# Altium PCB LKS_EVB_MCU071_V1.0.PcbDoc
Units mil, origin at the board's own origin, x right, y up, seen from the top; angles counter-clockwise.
Board outline 2625 x 1560 mil, 2 copper layers (Top Layer, Bottom Layer); 45 components, 64 nets, 192 pads, 49 vias.
Unrouted connection lines stored in the file: 4.
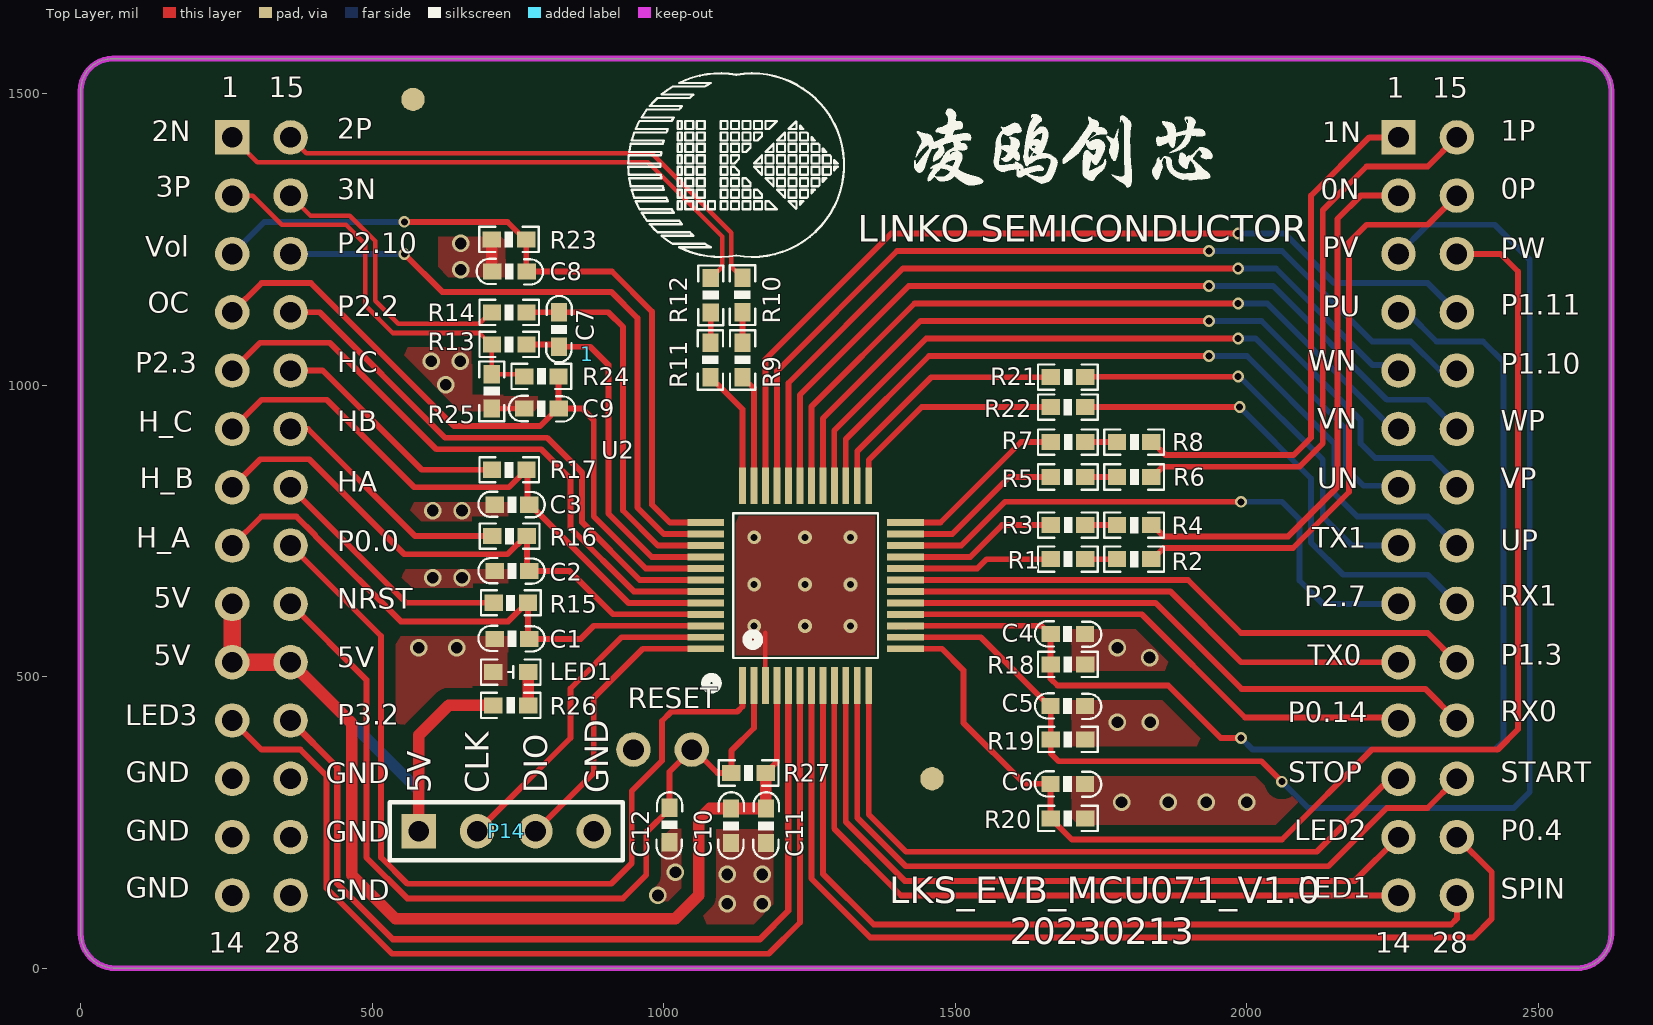
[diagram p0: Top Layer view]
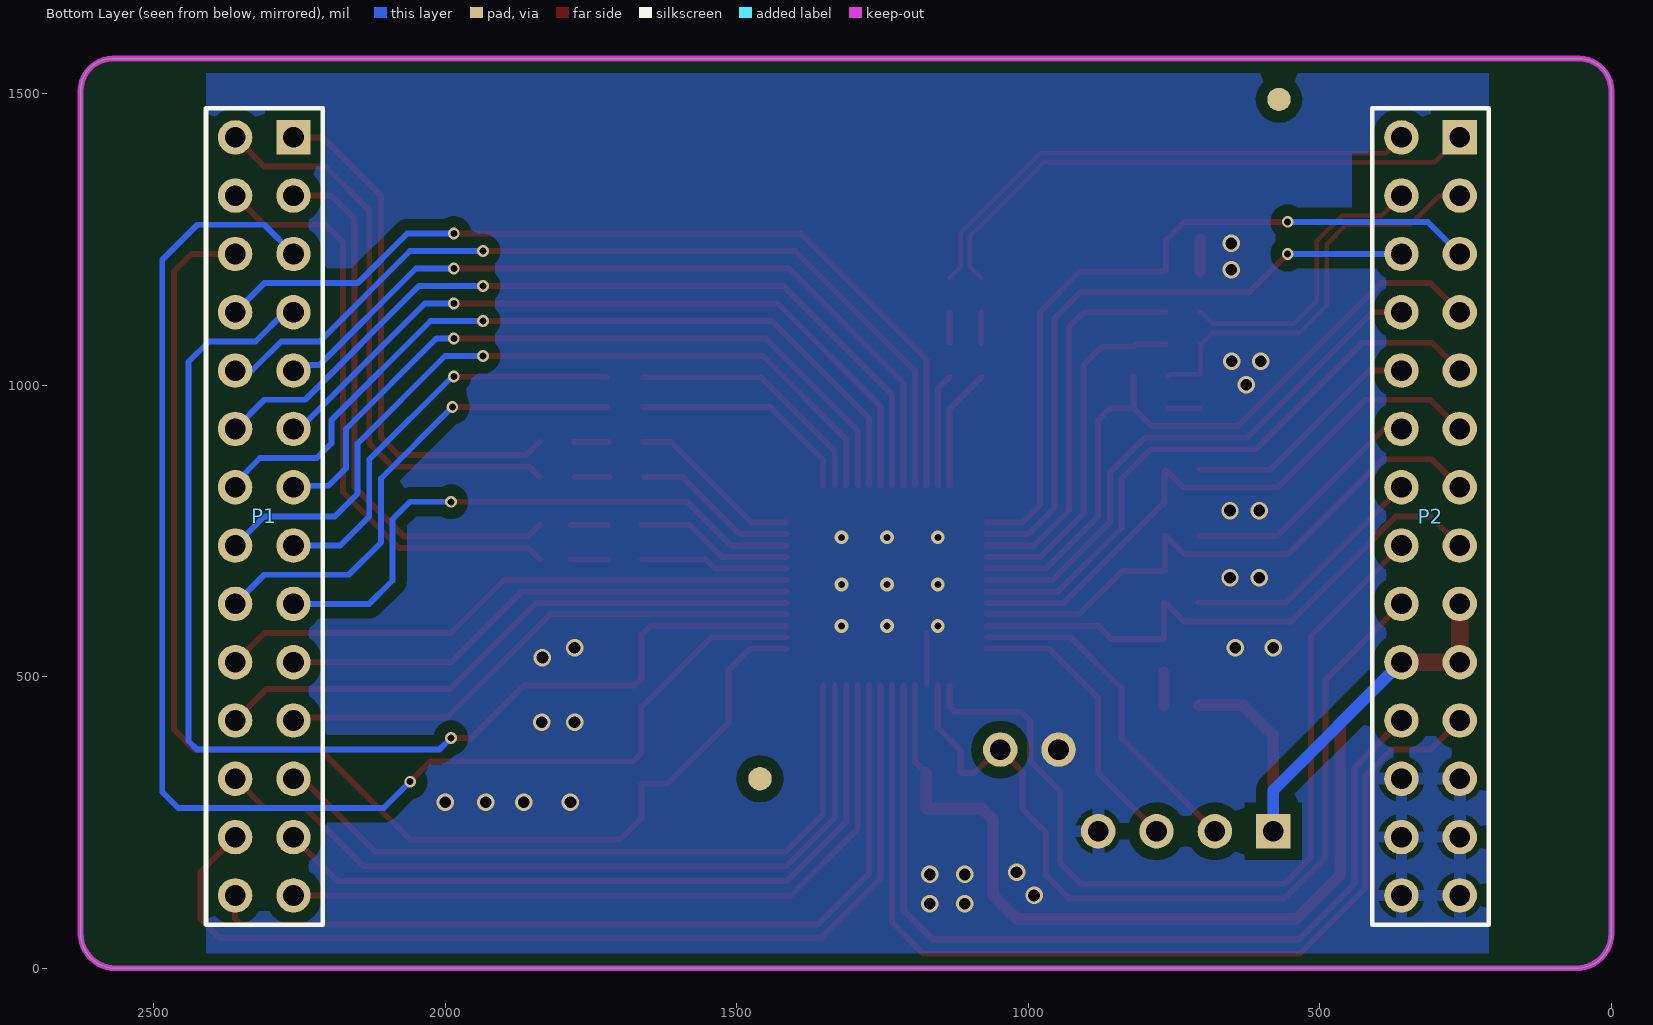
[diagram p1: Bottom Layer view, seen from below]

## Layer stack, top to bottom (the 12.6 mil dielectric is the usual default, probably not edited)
Top Solder: solder mask 0.4, Solder Resist, Dk 3.5
Top Layer: signal copper 1.4
Dielectric1: dielectric 12.6, FR-4, Dk 4.8
Bottom Layer: signal copper 1.4
Bottom Solder: solder mask 0.4, Solder Resist, Dk 3.5

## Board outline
0,60 0,1505 cw(c55,1505) 55,1560 2570,1560 cw(c2570,1505) 2625,1505 2625,60 cw(c2565,60) 2565,0 60,0 cw(c60,60)

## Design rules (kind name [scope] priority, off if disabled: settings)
Clearance Clearance_2 [InPolygon] p1: gap=20 ignorepadtopadclearanceinfootprint=FALSE except(0: Arc-Hole Track-Hole SMDPad-Hole THPad-Hole Via-Hole Fill-Hole Poly-Hole Region-Hole Text-Hole)
Clearance Clearance_1 [All] p2: gap=7.87 ignorepadtopadclearanceinfootprint=FALSE except(0: Arc-Hole Track-Hole SMDPad-Hole THPad-Hole Via-Hole Fill-Hole Poly-Hole Region-Hole Text-Hole)
ComponentClearance [All] p1: gap=0 collisioncheckmode=3 verticalgap=0 showdistances=FALSE
DiffPairsRouting [All] p1: maxlimit=10 minlimit=10 mostfreqgap=10 toplayer_minwidth=8 toplayer_maxwidth=15 toplayer_prefwidth=10 bottomlayer_minwidth=8 bottomlayer_maxwidth=15 bottomlayer_prefwidth=10 maxuncoupledlength=500
FabricationTestpoint [(IsPad And (OnTopLayer Or OnBottomLayer))] p1: side=3 testpointundercomponent=TRUE minsize=40 maxsize=100 preferedsize=60 minholesize=0 maxholesize=40 preferedholesize=32 testpointgrid=1 allowsidetop=TRUE allowsidebottom=TRUE usegrid=TRUE gridtolerance=0.01
HoleSize [All] p1: absolutevalues=TRUE maxlimit=100 minlimit=0 maxpercent=80.000 minpercent=20.000
PolygonConnect PolygonConnect_2 [HasFootprint('HDR1X4') vs InNet('GND')] p1: connectstyle=Relief reliefconductorwidth=20 reliefentries=4 polygonreliefangle="90 Angle" airgapwidth=10
PolygonConnect PolygonConnect_1 [HasFootprint('HDR2X14_CEN') vs InNet('GND')] p2: connectstyle=Relief reliefconductorwidth=20 reliefentries=4 polygonreliefangle="90 Angle" airgapwidth=10
PolygonConnect [All] p3: connectstyle=Direct reliefconductorwidth=10 reliefentries=4 polygonreliefangle="90 Angle" airgapwidth=10
RoutingVias [All] p1: holewidth=28 width=50 viastyle="Through Hole" minholewidth=0 minwidth=10 maxholewidth=28 maxwidth=50
SilkToSolderMaskClearance SilkscreenOverComponentPads [IsPad] p1: minsilkscreentomaskgap=10 clearancetoexposedcopper=TRUE
SolderMaskExpansion [All] p1: expansion=4 istentingtop=FALSE
Width [All] p1: maxlimit=100 minlimit=1 preferedwidth=10
25 further rules are at their usual default settings.

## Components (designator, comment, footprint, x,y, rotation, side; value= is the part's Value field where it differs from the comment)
1 "LKS_sign" LKS_LOGO2 868.94,1052.83 r0 top
C1 "10nF/50V" 0603C 769.06,565 r180 top
C2 "10nF/50V" 0603C 769.06,681.13 r180 top
C3 "10nF/50V" 0603C 769.06,795 r180 top
C4 "1nF/50V" 0603C 1663.34,573.64 r0 top
C5 "1nF/50V" 0603C 1663.2,450 r0 top
C6 "1nF/50V" 0603C 1663.2,316.45 r0 top
C7 "1nF/50V" 0603C 820,1065.94 r90 top
C8 "100nF/50V" 0603C 705.94,1195 r0 top
C9 "1nF/50V" 0603C 760.94,960 r0 top
C10 "10uF/16V" 0603C 1115,215 r90 top
C11 "100nF/50V" 0603C 1175,215 r90 top
C12 "100nF/50V" 0603C 1010,275.24 r270 top
LED1 "LED" "LED 0603R" 737.57,508 r180 top
P1 "Header 14X2A" HDR2X14_CEN 2260,1425 r270 bottom locked
P2 "Header 14X2A" HDR2X14_CEN 260,1425 r270 bottom locked
P14 "Header 4" HDR1X4 580,235 r0 top
R1 "20K1%" 0603R#1 1722.56,701.59 r180 top value=K
R2 "20K1%" 0603R#1 1836.22,701.59 r180 top value=K
R3 "20K1%" 0603R#1 1722.56,760 r180 top value=K
R4 "20K1%" 0603R#1 1836.22,760 r180 top value=K
R5 "20K1%" 0603R#1 1722.56,842.52 r180 top value=K
R6 "20K1%" 0603R#1 1836.22,842.52 r180 top value=K
R7 "20K1%" 0603R#1 1722.56,902.52 r180 top value=K
R8 "20K1%" 0603R#1 1836.22,902.52 r180 top value=K
R9 "20K1%" 0603R#1 1135.08,1072.79 r270 top value=K
R10 "20K1%" 0603R#1 1135,1184.06 r270 top value=K
R11 "20K1%" 0603R#1 1080.05,1072.79 r270 top value=K
R12 "20K1%" 0603R#1 1080.6,1183.74 r270 top value=K
R13 "1K1%" 0603R#1 705.5,1070 r0 top value=K
R14 "1K1%" 0603R#1 705.5,1125 r0 top value=K
R15 "2K" 0603R#1 708.22,626.9 r0 top value=K
R16 "2K" 0603R#1 706.13,741.13 r0 top value=K
R17 "2K" 0603R#1 705.5,855 r0 top value=K
R18 "1K" 0603R#1 1663.5,521.25 r0 top value=K
R19 "1K" 0603R#1 1663.5,392.6 r0 top value=K
R20 "1K" 0603R#1 1663.5,257.18 r0 top value=K
R21 "10R" 0603R#1 1722.56,1013.7 r180 top value=K
R22 "10R" 0603R#1 1663.5,962.52 r0 top value=K
R23 "1K1%" 0603R#1 705,1250 r0 top value=K
R24 "1K1%" 0603R#1 819.56,1015 r180 top value=K
R25 "10R" 0603R#1 705,1019.06 r270 top value=K
R26 "330R" 0603R#2 737.57,451 r0 top value=330
R27 "20K" 0603R#1 1115.94,335 r0 top value=K
U2 "LKS32MC071CBT8" TQFP48 1243.27,656.26 r0 top

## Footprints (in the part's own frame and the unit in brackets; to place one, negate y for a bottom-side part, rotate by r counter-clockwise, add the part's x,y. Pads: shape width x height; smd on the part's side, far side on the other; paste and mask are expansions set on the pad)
0603C [mm]
  rect 0.8x0.7 smd: 1(0,0) 2(1.5,0)
  silkscreen extent -0.68,-0.57 2.21,0.55
0603R#1 [mm]
  rect 0.8x0.7 smd: 1(0,0) 2(1.5,0)
  silkscreen extent -0.55,-0.55 2.05,0.55
0603R#2 [mm] "电阻"
  rect 0.8x0.7 smd: 1(-0.762,0) 2(0.762,0)
  silkscreen extent -1.3,-0.55 1.3,0.55, body extent -0.8,-0.4 0.8,0.4, height 0.45
HDR1X4 [mm] "Connector; Header; 4 Position"
  rect 1.5x1.5 hole 0.9: 1(0,0)
  round 1.5 hole 0.9: 2(2.54,0) 3(5.08,0) 4(7.62,0)
  silkscreen extent -1.27,-1.27 8.89,1.27
HDR2X14_CEN [mm] "Connector; Header; 14x2 Position"
  rect 1.5x1.5 hole 0.9: 1(0,0)
  round 1.5 hole 0.9: 2(2.54,0) 3(5.08,0) 4(7.62,0) 5(10.16,0) 6(12.7,0) 7(15.24,0) 8(17.78,0) 9(20.32,0) 10(22.86,0) 11(25.4,0) 12(27.94,0) 13(30.48,0) 14(33.02,0) 15(0,-2.54) 16(2.54,-2.54) 17(5.08,-2.54) 18(7.62,-2.54) 19(10.16,-2.54) 20(12.7,-2.54) 21(15.24,-2.54) 22(17.78,-2.54) 23(20.32,-2.54) 24(22.86,-2.54) 25(25.4,-2.54) 26(27.94,-2.54) 27(30.48,-2.54) 28(33.02,-2.54)
  silkscreen extent -1.27,-3.81 34.29,1.27
"LED 0603R" [mm] "LED"
  rect 0.8x0.7 smd: 1(-0.762,0) 2(0.762,0)
  silkscreen extent -1.3,-0.55 1.3,0.55, body extent -0.8,-0.4 0.8,0.4, height 0.47
LKS_LOGO2 [mil] "标?"
  silkscreen extent 70,167 440,482
TQFP48 [mm] "LINKO-081/083/088/051"
  rect 0.3x1.6 smd: 1(-2.75,-4.35) 2(-2.25,-4.35) 3(-1.75,-4.35) 4(-1.25,-4.35) 5(-0.75,-4.35) 6(-0.25,-4.35) 7(0.25,-4.35) 8(0.75,-4.35) 9(1.25,-4.35) 10(1.75,-4.35) 11(2.25,-4.35) 12(2.75,-4.35) 25(2.75,4.35) 26(2.25,4.35) 27(1.75,4.35) 28(1.25,4.35) 29(0.75,4.35) 30(0.25,4.35) 31(-0.25,4.35) 32(-0.75,4.35) 33(-1.25,4.35) 34(-1.75,4.35) 35(-2.25,4.35) 36(-2.75,4.35)
  rect 1.6x0.3 smd: 13(4.35,-2.75) 14(4.35,-2.25) 15(4.35,-1.75) 16(4.35,-1.25) 17(4.35,-0.75) 18(4.35,-0.25) 19(4.35,0.25) 20(4.35,0.75) 21(4.35,1.25) 22(4.35,1.75) 23(4.35,2.25) 24(4.35,2.75) 37(-4.35,2.75) 38(-4.35,2.25) 39(-4.35,1.75) 40(-4.35,1.25) 41(-4.35,0.75) 42(-4.35,0.25) 43(-4.35,-0.25) 44(-4.35,-0.75) 45(-4.35,-1.25) 46(-4.35,-1.75) 47(-4.35,-2.25) 48(-4.35,-2.75)
  silkscreen extent -4.35,-4.5 3.15,3.15, body extent -4.5,-4.5 4.5,4.5, height 1.05

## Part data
C1 C2 C3 C4 C5 C6: library part CAP, "Capacitor"
C7 C8 C9 C10 C11 C12: library part C, "Capacitor"
LED1: "LED_Light"
P1 P2: "Header, 14-Pin, Dual row"
P14: "Header, 4-Pin"
R1 R2 R3 R4 R5 R6 R7 R8 R9 R10 R11 R12 R13 R14 R15 R16 R17 R18 R19 R20 R21 R22 R23 R24 R25 R26 R27: library part Res, "Resistor"
U2: "芯片"

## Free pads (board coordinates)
  round 59.06 hole 35.43: 0(1048,375) 1(948,375)
  round 40 all layers, no hole: 2(1460,325) 3(570,1490)

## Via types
v1: diameter 30, hole 20, Top Layer to Bottom Layer, 25 vias
v2: diameter 20, hole 12, Top Layer to Bottom Layer, 15 vias
v3: diameter 23.62, hole 11.81, Top Layer to Bottom Layer, 9 vias

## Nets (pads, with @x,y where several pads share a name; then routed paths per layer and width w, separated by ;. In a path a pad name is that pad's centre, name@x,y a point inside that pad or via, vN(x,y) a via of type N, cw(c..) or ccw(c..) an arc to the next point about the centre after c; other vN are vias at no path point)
+5V: C10.2 C11.2 P2.9 P2.10 P2.24 P14.1 R26.1 R27.2 U2.4 | length 2417.7
  Top Layer w10: R27.2 1194.06,354.06 U2.4
  Top Layer w20: P2.24 465,420 465,160 540,85 1020,85 1060,125 1060,255 1079.06,274.06 C10.2 C11.2 R27.2 ; P14.1 580,400 631,451 R26.1
  Top Layer w30: P2.9 P2.10 P2.24
  Bottom Layer w20: P2.24 580,305 P14.1
GND: C1.2 C2.2 C3.2 C4.2 C5.2 C6.2 C8.1 C9.1 C10.1 C11.1 C12.2 LED1.2 P2.12 P2.13 P2.14 P2.16 P2.26 P2.27 P2.28 P14.4 pad.1 R14.1 R18.2 R19.2 R20.2 R23.1 R25.2 U2.3 | length 706.5
  Top Layer w7.87: P2.16 394.25,1290.75 461.52,1290.75 505,1247.27 505,1145 544.81,1105.19 683.72,1105.19 703.53,1125 R14.1 ; R25.2 C9.1 ; C8.1@705,1195.94 C8.1 ; U2.3 1174.37,575.51
  Top Layer w20: C8.1@705,1195.94 R23.1
  other v1: 1109,111 1169,111 990,125 1109,161 1169,161 1020,165 1785,285 1865,285 1930,285 2000,285 1778,422 1834,422 1833,533 580,550 645,550 1778,550 604,670 654,670 604,785 654,785 626,1001 601,1041 651,1041 652,1198 652,1243
  other v3: 1155,587.04 1242,587.04 1320,587.04 1155,658 1242,658 1320,658 1155,739.07 1242,739.07 1320,739.07
HALL_U: C1.1 P2.8 R15.2 U2.46 | length 991.2
  Top Layer w10: P2.8 310,775 369.96,775 402.4,742.56 402.4,741.55 548.95,595 733.41,595 765.31,626.9 R15.2 767.28,566.78 C1.1 857.64,565 880,587.36 U2.46
HALL_V: C2.1 P2.7 R16.2 U2.45 | length 1002.7
  Top Layer w10: P2.7 307.99,872.99 392.01,872.99 555,710 732.08,710 763.21,741.13 R16.2 765.65,740.66 765.65,681.13 838.87,681.13 912.95,607.05 U2.45
HALL_W: C3.1 P2.6 R17.2 U2.44 | length 1035.9
  Top Layer w10: P2.6 310,975 421.96,975 571.96,825 734.56,825 R17.2 766.33,853.23 766.33,795 C3.1 771.02,795 939.29,626.73 U2.44
HU: P2.21 R15.1 | length 430.3
  Top Layer w10: P2.21 558.1,626.9 R15.1
HV: P2.20 R16.1 | length 422.3
  Top Layer w10: P2.20 389.75,925 573.62,741.13 R16.1
HW: P2.19 R17.1 | length 415.9
  Top Layer w10: P2.19 415,1025 585,855 R17.1
LED1: P1.14 U2.9 | length 1260.4
  Top Layer w10: U2.9 1292.48,239.52 1407,125 P1.14
LED2: P1.13 U2.10 | length 1254.6
  Top Layer w10: U2.10 1312.17,251.15 1413.32,150 2185,150 P1.13
LED3: P2.11 U2.6 | length 1680.9
  Top Layer w10: P2.11 310,375 377.01,375 421.63,330.38 421.63,137.39 534.02,25 1180,25 1233.43,78.43 U2.6
NetLED1_1: LED1.1 R26.2 | length 57
  Top Layer w20: R26.2 LED1.1
NetR1_1: R1.1 R2.2 | length 63.6
  Top Layer w10: R1.1@1721.39,701.59 R2.2@1785,701.59
NetR3_1: R3.1 R4.2 | length 63.9
  Top Layer w10: R3.1@1721.1,760 R4.2@1785,760
NetR5_1: R5.1 R6.2 | length 59.1
  Top Layer w10: R5.1@1718.11,842.52 R6.2
NetR7_1: R7.1 R8.2 | length 59.1
  Top Layer w10: R7.1@1720.04,902.52 R8.2@1779.09,902.52
NetR9_1: R9.1 R10.2 | length 52.1
  Top Layer w10: R9.1@1135,1072.88 R10.2
NetR11_1: R11.1 R12.2 | length 51.3
  Top Layer w10: R11.1@1080.6,1073.34 R12.2
NetR21_2: R21.2 U2.26 | length 441
  Top Layer w10: U2.26 1331.85,886.85 1458.7,1013.7 R21.2@1660.98,1013.7
NetR22_1: R22.1 U2.25 | length 391.1
  Top Layer w10: U2.25 1351.54,871.54 1442.52,962.52 R22.1@1660.98,962.52
NRST: C12.1 P2.23 pad.0 R27.1 U2.2 | length 1512.3
  Top Layer w10: P2.23 490,495 490,190 560,120 930,120 970,160 970,233.27 1010,273.27 C12.1 1010,337 pad.0 1052,375 1092,335 R27.1 1115.94,373.26 1154.69,412 U2.2
OC: C9.2 P2.4 R24.1 U2.41 | length 1212
  Top Layer w10: P2.4 310,1175 395,1175 640,930 788.03,930 818.03,960 C9.2 ; R24.1 819.56,960.44 C9.2 ; U2.41 969.21,685.79 880,775 880,940 860,960 C9.2
OPA0_IN: R3.2 U2.21 | length 270.1
  Top Layer w10: U2.21 1525.47,705.47 1580,760 R3.2@1662.04,760
OPA0_IP: R1.2 U2.20 | length 254.4
  Top Layer w10: U2.20 1537.59,685.79 1553.39,701.59 R1.2@1662.34,701.59
OPA1_IN: R7.2 U2.24 | length 303.6
  Top Layer w10: U2.24 1474.53,764.53 1612.52,902.52 R7.2@1660.98,902.52
OPA1_IP: R5.2 U2.23 | length 285
  Top Layer w10: U2.23 1494.84,744.84 1592.52,842.52 R5.2@1659.06,842.52
OPA2_IN: R11.2 U2.36 | length 209
  Top Layer w10: R11.2 1135,958.79 U2.36
OPA2_IP: R9.2 U2.35 | length 194.3
  Top Layer w10: R9.2 1154.68,994.14 U2.35
OPA3_IN: C7.2 R14.2 U2.39 | length 657.6
  Top Layer w10: R14.2 C7.2 905,1125 930,1100 930,785 989.84,725.16 U2.39
OPA3_IP: C7.1 R13.2 U2.40 | length 607.8
  Top Layer w10: R13.2 815.94,1070 C7.1 874.06,1065.94 905,1035 905,780 979.53,705.47 U2.40
P0.0: P2.22 U2.1 | length 1512.2
  Top Layer w10: P2.22 515,570 515,190.28 560.28,145 910,145 945,180 945,304 997,356 997,424.18 1012.82,440 1126,440 1135,449 U2.1
P0.4: P1.27 U2.7 | length 1717.8
  Top Layer w10: U2.7 1253.11,154.05 1354.16,53 2388,53 2420,85 2420,165 P1.27
P0.14: P1.11 U2.16 | length 920.9
  Top Layer w10: U2.16 1819.69,607.05 1996.73,430 2255,430 P1.11
P1.3: P1.24 U2.19 | length 1003.9
  Top Layer w10: U2.19 1898.9,666.1 1990,575 2310,575 P1.24
P1.10: P1.19 U2.33 | length 1532.7
  Top Layer w10: U2.33 1194.06,1024.06 1400,1230 v2(1935,1230)
  Bottom Layer w10: v2(1935,1230) 2060,1230 2215,1075 2280.99,1075 2330.99,1025 P1.19
P1.11: P1.18 U2.34 | length 1547.7
  Top Layer w10: U2.34 1174.37,1044.37 1390,1260 v2(1985,1260)
  Bottom Layer w10: v2(1985,1260) 2065,1260 2150,1175 2310,1175 P1.18
P2.2: P2.18 U2.42 | length 951.9
  Top Layer w10: P2.18 410,1125 625,910 800,910 860,850 860,765 958.9,666.1 U2.42
P2.3: P2.5 U2.43 | length 1058.2
  Top Layer w10: P2.5 307.79,1072.79 427.21,1072.79 610,890 790,890 840,840 840,755 948.58,646.42 U2.43
P2.7: P1.9 U2.22 | length 1010.5
  Top Layer w10: U2.22 1510.16,725.16 1585,800 v2(1990,800)
  Bottom Layer w10: v2(1990,800) 2060,800 2090,770 2090,665 2130,625 P1.9
P2.10: P2.17 U2.38 | length 1101.3
  Top Layer w10: v2(555,1225) 620,1160 910,1160 955,1115 955,790 1000.16,744.84 U2.38
  Bottom Layer w10: P2.17 v2(555,1225)
P3.2: P2.25 U2.5 | length 1532.7
  Top Layer w11: P2.25 440,345 440,145 535,50 1165,50 1213.74,98.74 U2.5
PGND: P1.1 P1.2 P2.1 P2.2 R4.1 R8.1 R12.1 R13.1 R24.2 R25.1 | length 3566.5
  Top Layer w7.87: P2.2 295,1325 345,1275 455,1275 488.19,1241.81 488.19,1136.81 535.56,1089.44 684.09,1089.44 703.53,1070 R13.1 705,1069.5 R25.1 756.45,1019.06 R24.2 ; P2.1 302.91,1382.09 972.91,1382.09 1100,1255 1100,1203.14 R12.1 ; P1.1@2260,1412.38 P1.1
  Top Layer w10: R4.1 1838.19,760 1857.4,740.79 2070.79,740.79 2155.1,825.1 2155.1,1285.1 2195,1325 P1.2 ; R8.1@1838.19,902.52 1860.71,880 2080,880 2110,910 2110,1325 2210,1425 P1.1
PU: C4.1 P1.4 R18.1 U2.15 | length 2031.2
  Top Layer w10: U2.15@1415.43,586.46 U2.15 1647.65,587.36 1661.37,573.64 C4.1 1663.34,521.25 1663.34,496.66 1675,485 1865,485 1955,395 v2(1990,395)
  Bottom Layer w10: v2(1990,395) 2010,375 2425,375 2440,390 2440,1040 2405,1075 2325,1075 2275,1125 P1.4
PV: C5.1 P1.3 R19.1 U2.14 | length 2434
  Top Layer w10: U2.14 1543.55,567.68 1661.23,450 C5.1 1663.5,449.7 R19.1 1663.5,368.43 1676.93,355 2025,355 v2(2060,320)
  Bottom Layer w10: v2(2060,320) 2105.15,274.85 2457.48,274.85 2485,302.37 2485,1215 2424.98,1275.02 2310.02,1275.02 P1.3
PW: C6.1 P1.17 R20.1 U2.13 | length 2254
  Top Layer w10: U2.13 1477.01,547.99 1513.76,511.24 1513.76,421.24 1618.55,316.45 C6.1 R20.1@1663.2,257.34 ; R20.1@1663.35,257.18 1699.79,220.75 2060,220.75 2214.25,375 2430,375 2465,410 2465,1195 2435,1225 P1.17
RXD0: P1.25 U2.17 | length 1029
  Top Layer w10: U2.17 1843.27,626.73 1990.74,479.26 2305.74,479.26 P1.25
RXD1: P1.23 R22.2 | length 841.7
  Top Layer w10: R22.2 v2(1987.52,962.52)
  Bottom Layer w10: v2(1987.52,962.52) 2110,840.03 2110,730 2165,675 2310,675 P1.23
SPIN: P1.28 U2.8 | length 1490.3
  Top Layer w10: U2.8 1272.8,162.2 1360,75 2350,75 2360,85 P1.28
START1: P1.26 U2.11 | length 1351.6
  Top Layer w10: U2.11 1331.85,258.15 1415,175 2140,175 2239.85,274.85 2309.85,274.85 P1.26
STOP1: P1.12 U2.12 | length 1207.9
  Top Layer w10: U2.12 1351.54,263.74 1415.28,200 2119.72,200 2244.72,325 P1.12
SWCLK: P14.2 U2.47 | length 579.6
  Top Layer w10: P14.2 840,395 840,480 927.68,567.68 U2.47
SWDIO: P14.3 U2.48 | length 497.1
  Top Layer w10: P14.3 880,335 880,463.82 964.17,547.99 U2.48
TXD0: P1.10 U2.18 | length 895.8
  Top Layer w10: U2.18 1868.58,646.42 1990,525 P1.10
TXD1: P1.8 R21.1 | length 715.2
  Top Layer w10: R21.1 1723.21,1014.35 1984.35,1014.35 v2(1985,1015)
  Bottom Layer w10: v2(1985,1015) 1987.4,1015 2130,872.4 2130,775 2180,725 P1.8
UN: P1.7 U2.28 | length 1272.9
  Top Layer w10: U2.28 1292.48,922.48 1450,1080 v2(1985,1080)
  Bottom Layer w10: v2(1985,1080) 2015,1080 2170,925 2170,857.52 2200,827.52 2257.48,827.52 P1.7
UP: P1.22 U2.27 | length 1371.5
  Top Layer w10: U2.27 1312.17,907.17 1455,1050 v2(1935,1050)
  Bottom Layer w10: v2(1935,1050) 2000,1050 2150,900 2150,814.23 2189.22,775 2310,775 P1.22
UP-: P2.15 R10.1 | length 908.9
  Top Layer w7.87: P2.15 387.17,1397.83 979.44,1397.83 1115.75,1261.52 1115.75,1203.31 R10.1
VN: P1.6 U2.30 | length 1306.5
  Top Layer w10: U2.30 1253.11,963.11 1430,1140 v2(1985,1140)
  Bottom Layer w10: v2(1985,1140) 2035,1140 2250,925 P1.6 P1.6@2260,926.73
VOL_ADC: C8.2 P2.3 R23.2 U2.37 | length 1273.9
  Top Layer w10: v2(555,1280) 732.09,1280 762.09,1250 R23.2 764.06,1195.94 C8.2 911.13,1195 980,1126.13 980,795 1010.47,764.53 U2.37
  Bottom Layer w10: P2.3 315,1280 v2(555,1280)
VP: P1.21 U2.29 | length 1417.5
  Top Layer w10: U2.29 1272.8,942.8 1440,1110 v2(1935,1110)
  Bottom Layer w10: v2(1935,1110) 2025,1110 2195,940 2195,900 2220,875 2317.25,875 2360,832.25 P1.21
VP-: P1.15 R6.1 | length 999.4
  Top Layer w10: R6.1 1838.19,842.52 1855.67,860 2090,860 2130,900 2130,1300 2205,1375 2310,1375 P1.15
WN: P1.5 U2.32 | length 1376.3
  Top Layer w10: U2.32 1213.74,1003.74 1410,1200 v2(1985,1200)
  Bottom Layer w10: v2(1985,1200) 2050,1200 2215.61,1034.39 2250.61,1034.39 P1.5
WP: P1.20 U2.31 | length 1461.2
  Top Layer w10: U2.31 1233.43,983.43 1420,1170 v2(1935,1170)
  Bottom Layer w10: v2(1935,1170) 2045,1170 2240,975 2310,975 P1.20
WP-: P1.16 R2.1 | length 1032.9
  Top Layer w10: R2.1 1838.19,701.59 1857.4,720.79 2079.08,720.79 2175.1,816.82 2175.1,1245.1 2205,1275 2310,1275 P1.16

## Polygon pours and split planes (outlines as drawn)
GND on Top Layer "Top Layer-No Net 1" (solid, remove dead copper, pour order 4): 410,1560 410,0 2210,0 2210,1560
GND on Bottom Layer "Top Layer-No Net 1" (solid, remove dead copper, pour order 6): 210,1560 210,0 2410,0 2410,1560

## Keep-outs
Keep-Out Layer:
  the board outline again, w10

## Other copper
Top Layer:
  pour cut-out: 880,416 996,416 997,415 997,356 945,304 945,180 825,180 813,192 813,268 880,335
  pour cut-out: 472.58,1385 508.1,1385 613.34,1279.76 613.34,1185 614.08,1185 652.43,1146.65 723.31,1146.65 723.31,1083.78 714.53,1075 565.02,1075 365.02,1275 210,1275 210,1385
Bottom Layer:
  pour cut-out: 300,1395 302.83,1397.83 445,1397.83 445,1280 300,1280

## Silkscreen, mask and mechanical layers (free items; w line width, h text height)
Top Overlay:
  drawing of 7 lines, arcs and shapes, not listed
  text "2P" at 440,1411 h60
  text "1P" at 2435,1407 h60
  text "2N" at 121.7,1406 h60
  text "1N" at 2129,1405 h60
  text "3P" at 128.81,1311 h60
  text "0P" at 2434.94,1308 h60
  text "3N" at 439.94,1307 h60
  text "0N" at 2126.28,1307 h60
  text "P2.10" at 440,1214 h60
  text "Vol" at 110.82,1208 h60
  text "PV" at 2129.78,1207 h60
  text "PW" at 2435,1206 h60
  text "OC" at 115.43,1112 h60
  text "P1.11" at 2435,1109 h60
  text "P2.2" at 440,1106 h60
  text "PU" at 2130.22,1106 h60
  text "WN" at 2105.36,1013 h60
  text "HC" at 440,1010 h60
  text "P2.3" at 94.06,1009 h60
  text "P1.10" at 2435,1008 h60
  text "VN" at 2120.62,913 h60
  text "WP" at 2435,910 h60
  text "HB" at 440,909 h60
  text "H_C" at 99.17,908 h60
  text "H_B" at 101,811 h60
  text "UN" at 2121.01,811 h60
  text "VP" at 2434.94,811 h60
  text "HA" at 440,805 h60
  text "H_A" at 95.73,709 h60
  text "TX1" at 2112.07,709 h60
  text "UP" at 2434.94,705 h60
  text "P0.0" at 440,703 h60
  text "RX1" at 2435,610 h60
  text "P2.7" at 2098.25,609 h60
  text "5V" at 125.03,606 h60
  text "NRST" at 440,605 h60
  text "P1.3" at 2435,509 h60
  text "5V" at 125.03,508 h60
  text "TX0" at 2104.36,508 h60
  text "5V" at 439.94,504 h60
  text "RESET" at 938,434 h60
  text "RX0" at 2435,412 h60
  text "P0.14" at 2070.11,410 h60
  text "P3.2" at 440,406 h60
  text "LED3" at 76.52,405 h60
  text "GND" at 77.36,307 h60
  text "STOP" at 2071.11,307 h60
  text "START" at 2434.94,307 h60
  text "GND" at 420,305 h60
  text "5V" at 600,300 h40 r90
  text "CLK" at 700,300 h40 r90
  text "DIO" at 800,300 h40 r90
  text "GND" at 905,300 h40 r90
  text "LED2" at 2080.77,208 h60
  text "P0.4" at 2435,208 h60
  text "GND" at 77.36,207 h60
  text "GND" at 420,205 h60
  text "GND" at 77.36,109 h60
  text "LED1" at 2088.04,109 h60
  text "SPIN" at 2434.94,107 h60
  text "GND" at 420,105 h60
  text "LKS_EVB_MCU071_V1.0" at 1387,96 h78.74
  text "20230213" at 1593,26 h78.74
Top Solder:
  circle w77.95: c1460,325 r17.01
  circle w77.99: c570,1490 r17.01
Mechanical 1:
  the board outline again, w10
